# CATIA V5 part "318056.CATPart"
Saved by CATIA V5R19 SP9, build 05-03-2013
Part number: 318056
Source: Unknown
Bounding box of the stored display mesh (mm): x -689.306 to 68.166, y -250.508 to -117.73, z 198.129 to 590.152
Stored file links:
  D:\16-SIL\kale oto\R19_V1\318056.CATPart
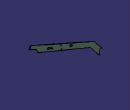
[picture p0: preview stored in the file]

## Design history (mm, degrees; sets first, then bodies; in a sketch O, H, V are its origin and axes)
Body1 "157\\126\\MANIFOLD_SOLID_BREP #79669" (main body)
  Solid1: solid without history
Body2 "241\\216\\MANIFOLD_SOLID_BREP #154205"
  Solid2: solid without history
Body3 "241\\217\\MANIFOLD_SOLID_BREP #153170"
  Solid3: solid without history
